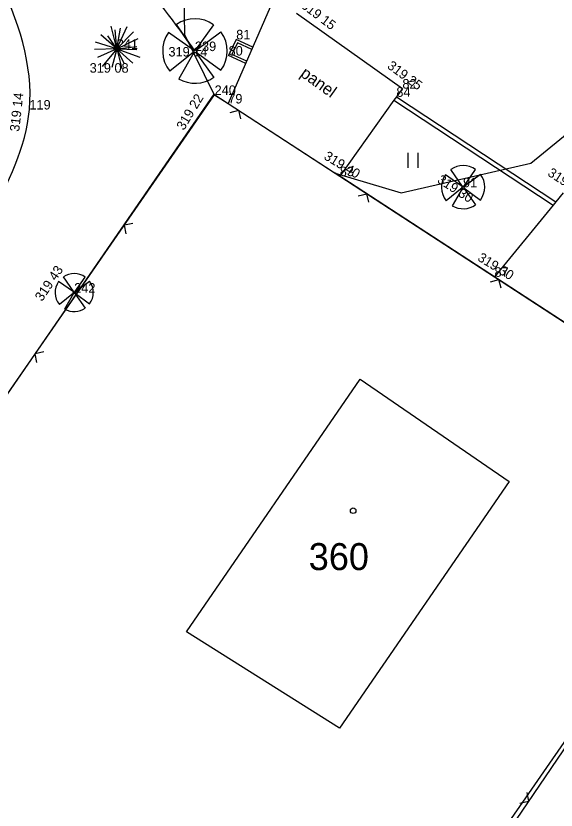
# Model space of a CAD drawing. Extents: x -742884 to -742543, y -1054677 to -1054433.
# Drawn here: x -742676.68 to -742659.68, y -1054548.61 to -1054523.59 of the extents above; entities that cross this region are included whole.
import ezdxf

# ---------------------------------------------------------------- set-up
doc = ezdxf.new("R2010")
doc.units = 0
for name, color, linetype in [('Vrstva 1', 7, 'Continuous'), ('Vrstva 10', 7, 'Continuous'), ('Vrstva 11', 7, 'Continuous'), ('Vrstva 13', 7, 'Continuous'), ('Vrstva 15', 7, 'Continuous'), ('Vrstva 2', 7, 'Continuous'), ('Vrstva 3', 7, 'Continuous'), ('Vrstva 4', 7, 'Continuous'), ('Vrstva 5', 7, 'Continuous'), ('Vrstva 50', 7, 'Continuous')]:
    doc.layers.add(name, color=color, linetype=linetype)

# ---------------------------------------------------------------- blocks, each defined once
blk = doc.blocks.new('Z15')
at = {"layer": 'Vrstva 2'}
for p, q in [((-10, 2), (-8, 6)), ((-10, -2), (-10, 2)), ((-8, 6), (-6, 8)), ((-6, 8), (-2, 10)), ((-2, 10), (2, 10)), ((2, 10), (6, 8)), ((6, 8), (8, 6)), ((8, 6), (10, 2)), ((10, 2), (10, -2)), ((-8, -6), (-10, -2)), ((-6, -8), (-8, -6)), ((-2, -10), (-6, -8)), ((2, -10), (-2, -10)), ((6, -8), (2, -10)), ((8, -6), (6, -8)), ((10, -2), (8, -6))]:
    blk.add_line(p, q, dxfattribs=at)

msp = doc.modelspace()

# ---------------------------------------------------------------- linework, layer by layer
at = {"layer": 'Vrstva 1'}
for p, q in [((-742669.75, -1054524.33), (-742669.75, -1054524.33)), ((-742673.51, -1054524.63), (-742673.51, -1054524.63)), ((-742671.05, -1054524.7), (-742671.05, -1054524.7)), ((-742669.99, -1054524.84), (-742669.99, -1054524.84)), ((-742670.43, -1054526.08), (-742670.43, -1054526.08)), ((-742664.52, -1054525.88), (-742664.52, -1054525.88)), ((-742670, -1054526.35), (-742670, -1054526.35)), ((-742664.71, -1054526.14), (-742664.71, -1054526.14)), ((-742676.26, -1054526.54), (-742676.26, -1054526.54)), ((-742666.49, -1054528.64), (-742666.49, -1054528.64)), ((-742662.61, -1054528.99), (-742662.61, -1054528.99)), ((-742659.69, -1054529.45), (-742659.69, -1054529.45)), ((-742661.62, -1054531.81), (-742661.62, -1054531.81)), ((-742674.85, -1054532.31), (-742674.85, -1054532.31))]:
    msp.add_line(p, q, dxfattribs=at)
at = {"layer": 'Vrstva 10'}
for p, q in [((-742673.51, -1054524.63), (-742673.687, -1054523.913)), ((-742673.51, -1054524.63), (-742673.555, -1054524.026)), ((-742673.51, -1054524.63), (-742673.18, -1054523.93)), ((-742673.51, -1054524.63), (-742673.387, -1054523.976)), ((-742673.51, -1054524.63), (-742672.983, -1054524.09)), ((-742671.09, -1054524.666), (-742671.878, -1054524.11)), ((-742671.074, -1054524.66), (-742671.628, -1054523.863)), ((-742671.02, -1054524.66), (-742670.459, -1054523.869)), ((-742671.012, -1054524.671), (-742670.232, -1054524.094)), ((-742673.51, -1054524.63), (-742674.011, -1054524.192)), ((-742673.51, -1054524.63), (-742673.792, -1054524.215)), ((-742673.51, -1054524.63), (-742672.834, -1054524.303)), ((-742673.51, -1054524.63), (-742674.175, -1054524.421)), ((-742673.51, -1054524.63), (-742672.875, -1054524.56)), ((-742673.51, -1054524.63), (-742674.211, -1054524.649)), ((-742673.51, -1054524.63), (-742674.116, -1054524.898)), ((-742673.51, -1054524.63), (-742673.969, -1054525.186)), ((-742673.51, -1054524.63), (-742673.664, -1054525.216)), ((-742673.516, -1054524.628), (-742673.516, -1054524.628)), ((-742673.51, -1054524.63), (-742673.51, -1054524.63)), ((-742673.51, -1054524.63), (-742673.284, -1054525.084)), ((-742673.51, -1054524.63), (-742672.779, -1054524.896)), ((-742673.51, -1054524.63), (-742672.875, -1054524.652)), ((-742673.51, -1054524.63), (-742673.003, -1054525.075)), ((-742673.51, -1054524.63), (-742673.349, -1054525.26)), ((-742673.51, -1054524.63), (-742673.51, -1054524.63)), ((-742671.091, -1054524.735), (-742671.84, -1054525.337)), ((-742671.08, -1054524.745), (-742671.561, -1054525.576)), ((-742671.016, -1054524.74), (-742670.458, -1054525.527)), ((-742671.006, -1054524.729), (-742670.232, -1054525.302)), ((-742664.348, -1054527.909), (-742664.348, -1054528.38)), ((-742664.034, -1054527.909), (-742664.034, -1054528.38)), ((-742662.635, -1054528.966), (-742663.165, -1054528.594)), ((-742662.626, -1054528.962), (-742662.996, -1054528.428)), ((-742662.59, -1054528.962), (-742662.215, -1054528.433)), ((-742662.584, -1054528.97), (-742662.062, -1054528.582)), ((-742662.637, -1054529.012), (-742663.138, -1054529.415)), ((-742662.63, -1054529.019), (-742662.952, -1054529.577)), ((-742662.588, -1054529.017), (-742662.214, -1054529.543)), ((-742662.581, -1054529.009), (-742662.062, -1054529.392)), ((-742674.864, -1054532.286), (-742675.191, -1054531.816)), ((-742674.832, -1054532.286), (-742674.501, -1054531.819)), ((-742674.874, -1054532.289), (-742675.34, -1054531.961)), ((-742674.828, -1054532.293), (-742674.368, -1054531.952)), ((-742674.874, -1054532.33), (-742675.317, -1054532.686)), ((-742674.867, -1054532.337), (-742675.152, -1054532.827)), ((-742674.831, -1054532.334), (-742674.501, -1054532.798)), ((-742674.824, -1054532.328), (-742674.368, -1054532.665))]:
    msp.add_line(p, q, dxfattribs=at)
for centre, radius, start, end in [((-742671.048, -1054524.697), 1.016, 54.7465, 124.8105), ((-742671.049, -1054524.695), 1.016, 144.8767, 218.9336), ((-742671.048, -1054524.697), 1.016, 323.4756, 36.2971), ((-742671.048, -1054524.697), 1.016, 239.6151, 305.4552), ((-742662.608, -1054528.987), 0.68, 54.7465, 124.8105), ((-742662.609, -1054528.986), 0.68, 144.8767, 218.9336), ((-742662.608, -1054528.987), 0.68, 323.4756, 36.2971), ((-742662.608, -1054528.987), 0.68, 239.6151, 305.4552), ((-742674.849, -1054532.308), 0.6, 54.7465, 124.8105), ((-742674.85, -1054532.307), 0.6, 144.8767, 218.9336), ((-742674.849, -1054532.308), 0.6, 323.4756, 36.2971), ((-742674.849, -1054532.308), 0.6, 239.6151, 305.4552)]:
    msp.add_arc(centre, radius, start, end, dxfattribs=at)
at = {"layer": 'Vrstva 11'}
for points in [[(-742776.7, -1054542.68), (-742764.01, -1054527.79), (-742751.11, -1054512.75), (-742737.61, -1054496.47), (-742726.42, -1054483.98), (-742725.9, -1054484.03), (-742714, -1054491.86), (-742704.819, -1054497.481), (-742700.94, -1054500.269), (-742696.44, -1054503.39), (-742688.83, -1054509.5), (-742682.54, -1054514.17), (-742675.15, -1054519.77), (-742673.01, -1054522.11), (-742671.05, -1054524.7)], [(-742641.45, -1054542), (-742646.08, -1054542.32), (-742650.28, -1054545.1), (-742653.63, -1054549.14), (-742658.66, -1054557.13), (-742664.13, -1054565.84), (-742667.81, -1054569.62), (-742669.76, -1054570.07), (-742674.4, -1054567.88), (-742684.66, -1054562.03), (-742693.02, -1054556.88), (-742694.43, -1054554.37), (-742693.99, -1054552.67), (-742684.52, -1054539.64), (-742677.51, -1054529.95), (-742676.26, -1054526.54), (-742677.27, -1054522.39), (-742681.19, -1054517.29), (-742689.28, -1054510.73), (-742697.86, -1054505.14), (-742704.02, -1054502.75), (-742713.11, -1054501.07), (-742723.98, -1054503.51), (-742736.77, -1054510.1), (-742745.39, -1054515.75), (-742752.81, -1054521.82), (-742762.72, -1054531.38), (-742770.54, -1054539.36), (-742775.54, -1054544.64)]]:
    msp.add_spline(points, degree=3, dxfattribs=at)
at = {"layer": 'Vrstva 13'}
for p, q in [((-742668.68, -1054523.32), (-742670, -1054526.35)), ((-742669.75, -1054524.33), (-742669.99, -1054524.84)), ((-742669.227, -1054524.576), (-742669.75, -1054524.33)), ((-742669.712, -1054524.436), (-742669.884, -1054524.802)), ((-742669.259, -1054524.649), (-742669.712, -1054524.436)), ((-742669.452, -1054525.093), (-742669.99, -1054524.84)), ((-742669.42, -1054525.02), (-742669.884, -1054524.802)), ((-742664.786, -1054526.246), (-742666.49, -1054528.64)), ((-742659.773, -1054529.551), (-742661.62, -1054531.81))]:
    msp.add_line(p, q, dxfattribs=at)
at = {"layer": 'Vrstva 4'}
for p, q in [((-742664.786, -1054526.246), (-742659.773, -1054529.551)), ((-742664.71, -1054526.14), (-742659.69, -1054529.45))]:
    msp.add_line(p, q, dxfattribs=at)
for points in [[(-742667.85, -1054523.5), (-742664.52, -1054525.88), (-742664.71, -1054526.14), (-742664.786, -1054526.246)], [(-742659.46, -1054529.17), (-742659.69, -1054529.45), (-742659.773, -1054529.551)]]:
    msp.add_lwpolyline(points, dxfattribs=at)
msp.add_spline([(-742718.8, -1054478.84), (-742709.4, -1054484.88), (-742695.99, -1054493.43), (-742680.4, -1054503.55), (-742661.01, -1054516), (-742635.78, -1054532.31)], degree=3, dxfattribs=at)
at = {"layer": 'Vrstva 5'}
for p, q in [((-742669.937, -1054526.63), (-742669.671, -1054526.565)), ((-742669.601, -1054526.833), (-742669.671, -1054526.565)), ((-742665.908, -1054529.257), (-742665.642, -1054529.192)), ((-742665.572, -1054529.46), (-742665.642, -1054529.192)), ((-742673.002, -1054530.128), (-742673.271, -1054530.185)), ((-742673.219, -1054530.455), (-742673.271, -1054530.185)), ((-742661.749, -1054531.964), (-742661.483, -1054531.899)), ((-742661.413, -1054532.167), (-742661.483, -1054531.899)), ((-742675.806, -1054534.179), (-742676.075, -1054534.236)), ((-742676.023, -1054534.506), (-742676.075, -1054534.236)), ((-742653.09, -1054537.35), (-742666.116, -1054556.522)), ((-742660.604, -1054548.059), (-742660.549, -1054548.328)), ((-742660.818, -1054548.388), (-742660.549, -1054548.328))]:
    msp.add_line(p, q, dxfattribs=at)
for points in [[(-742687.06, -1054550.12), (-742678.97, -1054538.42), (-742670.43, -1054526.08)], [(-742670.43, -1054526.08), (-742670, -1054526.35), (-742666.49, -1054528.64), (-742661.62, -1054531.81), (-742658.07, -1054534.12), (-742653.09, -1054537.35)]]:
    msp.add_lwpolyline(points, dxfattribs=at)
at = {"layer": 'Vrstva 50'}
msp.add_line((-742670.45, -1054526.06), (-742666.64, -1054528.55), dxfattribs=at)
for points in [[(-742724.95, -1054484.46), (-742672.19, -1054519.91), (-742671.42, -1054521.73), (-742671.38, -1054524.18), (-742670.45, -1054526.06)], [(-742670.45, -1054526.06), (-742684.78, -1054546.85), (-742687.08, -1054550.18), (-742679.03, -1054555.7), (-742669.36, -1054562.14), (-742666.55, -1054557.95), (-742665.76, -1054556.77), (-742666.29, -1054556.4), (-742653.11, -1054537.36), (-742666.64, -1054528.55)], [(-742666.64, -1054528.55), (-742664.56, -1054529.16), (-742660.48, -1054528.23), (-742659.05, -1054527.06), (-742630.9, -1054544.89), (-742546.289, -1054602.738)], [(-742665.85, -1054535.04), (-742661.16, -1054538.26), (-742666.5, -1054546.03), (-742671.32, -1054542.99), (-742665.85, -1054535.04)]]:
    msp.add_lwpolyline(points, dxfattribs=at)
msp.add_circle((-742666.068, -1054539.18), 0.0875, dxfattribs=at)

# ---------------------------------------------------------------- block references
at = {"layer": 'Vrstva 10', "rotation": -30.671756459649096}
for p, xscale, yscale in [((-742671.05, -1054524.7), 0.005079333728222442, 0.005079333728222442), ((-742662.61, -1054528.99), 0.0034002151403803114, 0.003400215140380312), ((-742674.85, -1054532.31), 0.0029992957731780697, 0.0029992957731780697)]:
    msp.add_blockref('Z15', p, dxfattribs=dict(at, xscale=xscale, yscale=yscale))

# ---------------------------------------------------------------- texts
at = {"layer": 'Vrstva 15'}
msp.add_text('panel', height=0.3751, rotation=324.2494, dxfattribs=at).set_placement((-742667.761, -1054525.471))
at = {"layer": 'Vrstva 2'}
for s, p in [('81', (-742669.75, -1054524.33)), ('241', (-742673.51, -1054524.63)), ('239', (-742671.05, -1054524.7)), ('80', (-742669.99, -1054524.84)), ('82', (-742664.52, -1054525.88)), ('240', (-742670.43, -1054526.08)), ('84', (-742664.71, -1054526.14)), ('79', (-742670, -1054526.35)), ('119', (-742676.26, -1054526.54)), ('83', (-742666.49, -1054528.64)), ('91', (-742662.61, -1054528.99)), ('87', (-742661.62, -1054531.81)), ('242', (-742674.85, -1054532.31))]:
    msp.add_text(s, height=0.3, dxfattribs=at).set_placement(p)
at = {"layer": 'Vrstva 3'}
for s, rotation, p in [('319 15 ', 322.8485, (-742667.736, -1054523.311)), ('319 25 ', 323.5991, (-742665.019, -1054525.219)), ('319 14 ', 83.8082, (-742676.581, -1054527.247)), ('319 22 ', 59.0362, (-742671.396, -1054527.216)), ('319 40 ', 328.5801, (-742667.014, -1054528.088)), ('319 30 ', 326.9657, (-742663.446, -1054528.823)), ('319 17 ', 327.038, (-742659.971, -1054528.606)), ('319 30 ', 328.3392, (-742662.175, -1054531.282)), ('319 43 ', 56.3099, (-742675.861, -1054532.605))]:
    msp.add_text(s, height=0.3, rotation=rotation, dxfattribs=at).set_placement(p)
for s, p in [('319 14 ', (-742671.883, -1054524.87)), ('319 08 ', (-742674.363, -1054525.38))]:
    msp.add_text(s, height=0.3, dxfattribs=at).set_placement(p)
at = {"layer": 'Vrstva 50'}
msp.add_text('360', height=0.85, dxfattribs=at).set_placement((-742667.468, -1054541.05))

doc.saveas('drawing.dxf')
